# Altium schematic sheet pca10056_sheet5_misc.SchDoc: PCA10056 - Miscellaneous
size A3; Organization: Nordic Semiconductor; DocumentNumber: 5; SheetNumber: 5; SheetTotal: 7; CompanyName: Nordic Semiconductor
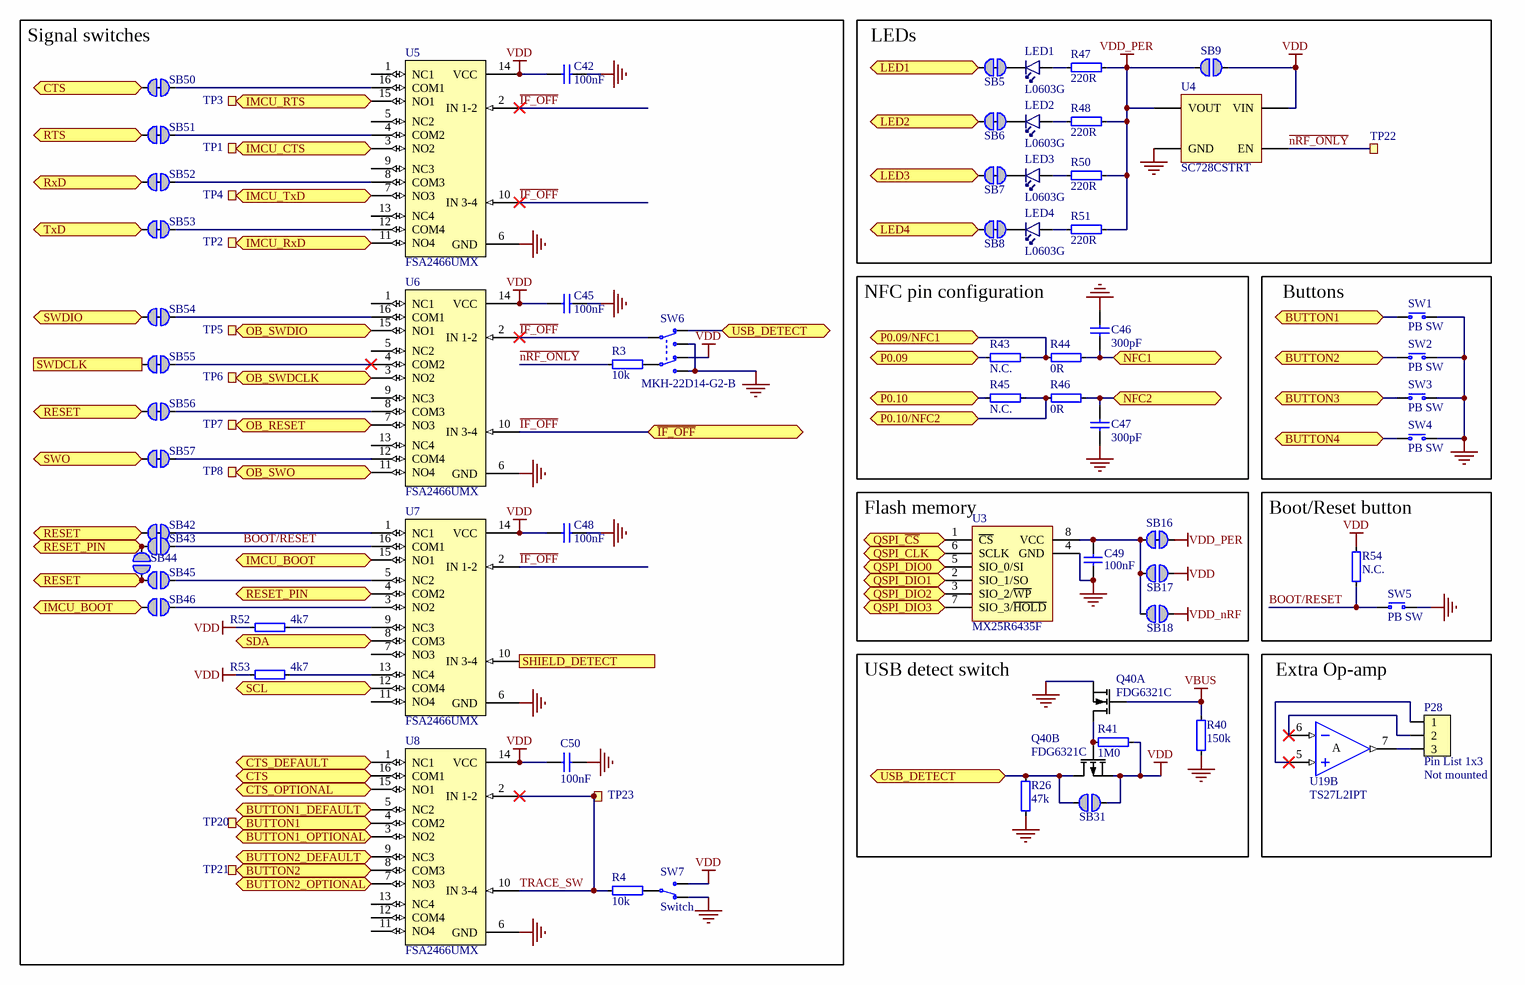
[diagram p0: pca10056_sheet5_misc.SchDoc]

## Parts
C42  100nF  [CAPC1005X04L]
C45  100nF  [CAPC1005X04L]
C46  300pF  [CAPC1005X04L]
C47  300pF  [CAPC1005X04L]
C48  100nF  [CAPC1005X04L]
C49  100nF  [CAPC1005X04L]
C50  100nF  [CAPC1005X04L]
LED1  L0603G  [LED_0603_G]
LED2  L0603G  [LED_0603_G]
LED3  L0603G  [LED_0603_G]
LED4  L0603G  [LED_0603_G]
P28  Pin List 1x3  Assembly: Not mounted  [LIST_1x3-NC]
Q40  FDG6321C  [SOT65P210X100-6N]  (parts A,B of 2)
R3  10k  [RESC1005X04L]
R4  10k  [RESC1005X04L]
R26  47k  [RESC1005X04L]
R40  150k  [RESC1005X04L]
R41  1M0  [RESC1005X04L]
R43  N.C.  [RESC1005X04L]
R44  0R  [RESC1005X04L]
R45  N.C.  [RESC1005X04L]
R46  0R  [RESC1005X04L]
R47  220R  [RESC1005X04L]
R48  220R  [RESC1005X04L]
R50  220R  [RESC1005X04L]
R51  220R  [RESC1005X04L]
R52  4k7  [RESC1005X04L]
R53  4k7  [RESC1005X04L]
R54  N.C.  [RESC1005X04L]
SB5  Solderbridge  [Solderbridge_Shorted]  (value not drawn)  (net tie, no BOM)
SB6  Solderbridge  [Solderbridge_Shorted]  (value not drawn)  (net tie, no BOM)
SB7  Solderbridge  [Solderbridge_Shorted]  (value not drawn)  (net tie, no BOM)
SB8  Solderbridge  [Solderbridge_Shorted]  (value not drawn)  (net tie, no BOM)
SB9  Solderbridge  [Solderbridge]  (value not drawn)  (no BOM)
SB16  Solderbridge  [Solderbridge_Shorted]  (value not drawn)  (net tie, no BOM)
SB17  Solderbridge  [Solderbridge]  (value not drawn)  (no BOM)
SB18  Solderbridge  [Solderbridge]  (value not drawn)  (no BOM)
SB31  Solderbridge  [Solderbridge]  (value not drawn)  (no BOM)
SB42  Solderbridge  [Solderbridge_Shorted]  (value not drawn)  (net tie, no BOM)
SB43  Solderbridge  [Solderbridge]  (value not drawn)  (no BOM)
SB44  Solderbridge  [Solderbridge]  (value not drawn)  (no BOM)
SB45  Solderbridge  [Solderbridge]  (value not drawn)  (no BOM)
SB46  Solderbridge  [Solderbridge]  (value not drawn)  (no BOM)
SB50  Solderbridge  [Solderbridge_Shorted]  (value not drawn)  (net tie, no BOM)
SB51  Solderbridge  [Solderbridge_Shorted]  (value not drawn)  (net tie, no BOM)
SB52  Solderbridge  [Solderbridge_Shorted]  (value not drawn)  (net tie, no BOM)
SB53  Solderbridge  [Solderbridge_Shorted]  (value not drawn)  (net tie, no BOM)
SB54  Solderbridge  [Solderbridge_Shorted]  (value not drawn)  (net tie, no BOM)
SB55  Solderbridge  [Solderbridge_Shorted]  (value not drawn)  (net tie, no BOM)
SB56  Solderbridge  [Solderbridge_Shorted]  (value not drawn)  (net tie, no BOM)
SB57  Solderbridge  [Solderbridge_Shorted]  (value not drawn)  (net tie, no BOM)
SW1  PB SW  [Switch-PB-6.2x6.3mm-SMD]
SW2  PB SW  [Switch-PB-6.2x6.3mm-SMD]
SW3  PB SW  [Switch-PB-6.2x6.3mm-SMD]
SW4  PB SW  [Switch-PB-6.2x6.3mm-SMD]
SW5  PB SW  [Switch-PB-6.2x6.3mm-SMD]
SW6  MKH-22D14-G2-B  [MKH-22D14-G2-B]
SW7  Switch  [CJS-120xA]
TP1  Ø1.0mm,SMD  [TP_SMD_Ø1.0mm]  (value not drawn)  (no BOM)
TP2  Ø1.0mm,SMD  [TP_SMD_Ø1.0mm]  (value not drawn)  (no BOM)
TP3  Ø1.0mm,SMD  [TP_SMD_Ø1.0mm]  (value not drawn)  (no BOM)
TP4  Ø1.0mm,SMD  [TP_SMD_Ø1.0mm]  (value not drawn)  (no BOM)
TP5  Ø1.0mm,SMD  [TP_SMD_Ø1.0mm]  (value not drawn)  (no BOM)
TP6  Ø1.0mm,SMD  [TP_SMD_Ø1.0mm]  (value not drawn)  (no BOM)
TP7  Ø1.0mm,SMD  [TP_SMD_Ø1.0mm]  (value not drawn)  (no BOM)
TP8  Ø1.0mm,SMD  [TP_SMD_Ø1.0mm]  (value not drawn)  (no BOM)
TP20  Ø1.0mm,SMD  [TP_SMD_Ø1.0mm]  (value not drawn)  (no BOM)
TP21  Ø1.0mm,SMD  [TP_SMD_Ø1.0mm]  (value not drawn)  (no BOM)
TP22  Ø1.0mm,SMD  [TP_SMD_Ø1.0mm]  (value not drawn)  (no BOM)
TP23  Ø1.0mm,SMD  [TP_SMD_Ø1.0mm]  (value not drawn)  (no BOM)
U3  MX25R6435F  [SON127P600X80_HS-9N]
U4  SC728CSTRT  [BGA4C40P2X2_76X76X62]
U5  FSA2466UMX  [XQFN40P180X260X50-16N]
U6  FSA2466UMX  [XQFN40P180X260X50-16N]
U7  FSA2466UMX  [XQFN40P180X260X50-16N]
U8  FSA2466UMX  [XQFN40P180X260X50-16N]
U19  TS27L2IPT  [TSOP65P640X120-8N]  (part B of 2)

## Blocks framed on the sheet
Signal switches: C42 C45 C48 C50 R3 R4 R52 R53 SB42-SB46 SB50-SB57 SW6 SW7 TP1-TP8 TP20 TP21 TP23 U5-U8
LEDs: LED1-LED4 R47 R48 R50 R51 SB5-SB9 TP22 U4
NFC pin configuration: C46 C47 R43-R46
Buttons: SW1-SW4
Flash memory: C49 SB16-SB18 U3
Boot/Reset button: R54 SW5
USB detect switch: Q40 R26 R40 R41 SB31
Extra Op-amp: P28 U19

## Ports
BUTTON1 (bidir), BUTTON1_DEFAULT (bidir), BUTTON1_OPTIONAL (bidir), BUTTON2 (bidir), BUTTON2_DEFAULT (bidir), BUTTON2_OPTIONAL (bidir), BUTTON3 (bidir), BUTTON4 (bidir), CTS (bidir), CTS_DEFAULT (bidir), CTS_OPTIONAL (bidir), IMCU_BOOT (bidir), IMCU_CTS (bidir), IMCU_RTS (bidir), IMCU_RxD (bidir), IMCU_TxD (bidir), LED1 (bidir), LED2 (bidir), LED3 (bidir), LED4 (bidir), NFC1 (bidir), NFC2 (bidir), OB_RESET (bidir), OB_SWDCLK (bidir), OB_SWDIO (bidir), OB_SWO (bidir), P0.09 (bidir), P0.09/NFC1 (bidir), P0.10 (bidir), P0.10/NFC2 (bidir), QSPI_CLK (bidir), QSPI_DIO0 (bidir), QSPI_DIO1 (bidir), QSPI_DIO2 (bidir), QSPI_DIO3 (bidir), QSPI_~{CS} (bidir), RESET (bidir), RESET_PIN (bidir), RTS (bidir), RxD (bidir), SCL (bidir), SDA (bidir), SHIELD_DETECT (in), SWDCLK (out), SWDIO (bidir), SWO (bidir), TxD (bidir), USB_DETECT (bidir), ~{IF_OFF} (bidir)

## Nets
GND: C42.1 C45.1 C46.2 C47.1 C48.1 C49.1 C50.1 Q40.1(S1) R26.2 R40.2 SW1.1(N.O) SW2.1(N.O) SW3.1(N.O) SW4.1(N.O) SW5.1(N.O) SW6.1(N.O-1) SW6.4(N.O-2) SW7.1(N.C) U3.4(GND) U3.9(GND) U4.B1(GND) U5.6(GND) U6.6(GND) U7.6(GND) U8.6(GND)
VBUS: Q40.2(G1) R40.1
VDD: C42.2 C45.2 C48.2 C50.2 Q40.4(S2) R41.1 R52.1 R53.1 R54.2 SB9.1 SB17.1 SB31.1 SW6.6(N.C-2) SW7.3(N.O) U4.A2(VIN) U5.14(VCC) U6.14(VCC) U7.14(VCC) U8.14(VCC)
VDD_nRF: SB18.1
VDD_PER: R47.2 R48.2 R50.2 R51.2 SB9.2 SB16.1 U4.A1(VOUT)
BOOT/RESET: R54.1 SB43.1 SW5.2(COM) U7.16(COM1)
BUTTON1: SW1.2(COM) TP20.1 U8.4(COM2) ; port BUTTON1
BUTTON1_DEFAULT: U8.5(NC2) ; port BUTTON1_DEFAULT
BUTTON1_OPTIONAL: U8.3(NO2) ; port BUTTON1_OPTIONAL
BUTTON2: SW2.2(COM) TP21.1 U8.8(COM3) ; port BUTTON2
BUTTON2_DEFAULT: U8.9(NC3) ; port BUTTON2_DEFAULT
BUTTON2_OPTIONAL: U8.7(NO3) ; port BUTTON2_OPTIONAL
BUTTON3: SW3.2(COM) ; port BUTTON3
BUTTON4: SW4.2(COM) ; port BUTTON4
CTS: SB50.1 U8.16(COM1) ; port CTS
CTS_DEFAULT: U8.1(NC1) ; port CTS_DEFAULT
CTS_OPTIONAL: U8.15(NO1) ; port CTS_OPTIONAL
~{IF_OFF}: SW6.2(COM-1) U5.2(IN_1-2) U5.10(IN_3-4) U6.2(IN_1-2) U6.10(IN_3-4) U7.2(IN_1-2) ; port ~{IF_OFF}
IMCU_BOOT: SB46.2 U7.15(NO1) ; port IMCU_BOOT
IMCU_CTS: TP1.1 U5.3(NO2) ; port IMCU_CTS
IMCU_RTS: TP3.1 U5.15(NO1) ; port IMCU_RTS
IMCU_RxD: TP2.1 U5.11(NO4) ; port IMCU_RxD
IMCU_TxD: TP4.1 U5.7(NO3) ; port IMCU_TxD
LED1: SB5.1 ; port LED1
LED2: SB6.1 ; port LED2
LED3: SB7.1 ; port LED3
LED4: SB8.1 ; port LED4
~{nRF_ONLY}: R3.1 TP22.1 U4.B2(EN)
NFC1: C46.1 R44.1 ; port NFC1
NFC2: C47.2 R46.1 ; port NFC2
OB_RESET: TP7.1 U6.7(NO3) ; port OB_RESET
OB_SWDCLK: TP6.1 U6.3(NO2) ; port OB_SWDCLK
OB_SWDIO: TP5.1 U6.15(NO1) ; port OB_SWDIO
OB_SWO: TP8.1 U6.11(NO4) ; port OB_SWO
P0.09: R43.1 ; port P0.09
P0.09/NFC1: R43.2 R44.2 ; port P0.09/NFC1
P0.10: R45.1 ; port P0.10
P0.10/NFC2: R45.2 R46.2 ; port P0.10/NFC2
QSPI_~{CS}: U3.1(~{CS}) ; port QSPI_~{CS}
QSPI_CLK: U3.6(SCLK) ; port QSPI_CLK
QSPI_DIO0: U3.5(SIO_0/SI) ; port QSPI_DIO0
QSPI_DIO1: U3.2(SIO_1/SO) ; port QSPI_DIO1
QSPI_DIO2: U3.3(SIO_2/~{WP}) ; port QSPI_DIO2
QSPI_DIO3: U3.7(SIO_3/~{HOLD}) ; port QSPI_DIO3
RESET: SB42.2 SB44.2 SB45.2 SB56.1 ; port RESET
RESET_PIN: SB43.2 SB44.1 U7.4(COM2) ; port RESET_PIN
RTS: SB51.1 ; port RTS
RxD: SB52.1 ; port RxD
SCL: U7.12(COM4) ; port SCL
SDA: U7.8(COM3) ; port SDA
SHIELD_DETECT: U7.10(IN_3-4) ; port SHIELD_DETECT
SWDCLK: SB55.1 ; port SWDCLK
SWDIO: SB54.1 ; port SWDIO
SWO: SB57.1 ; port SWO
TRACE_SW: R4.1 TP23.1 U8.2(IN_1-2) U8.10(IN_3-4)
TxD: SB53.1 ; port TxD
USB_DETECT: Q40.3(D2) R26.1 SB31.2 SW6.3(N.C-1) ; port USB_DETECT
NetC49_2: C49.2 SB16.2 SB17.2 SB18.2 U3.8(VCC)
NetLED1_1: LED1.1(C) SB5.2
NetLED1_2: LED1.2(A) R47.1
NetLED2_1: LED2.1(C) SB6.2
NetLED2_2: LED2.2(A) R48.1
NetLED3_1: LED3.1(C) SB7.2
NetLED3_2: LED3.2(A) R50.1
NetLED4_1: LED4.1(C) SB8.2
NetLED4_2: LED4.2(A) R51.1
NetP28_1: P28.1 U19.5(IN2+)
NetP28_2: P28.2 U19.6(IN2-)
NetP28_3: P28.3 U19.7(OUT2)
NetQ40_5: Q40.5(G2) Q40.6(D1) R41.2
NetR3_2: R3.2 SW6.5(COM-2)
NetR4_2: R4.2 SW7.2(COM)
NetR52_2: R52.2 U7.9(NC3)
NetR53_2: R53.2 U7.13(NC4)
NetSB42_1: SB42.1 U7.1(NC1)
NetSB45_1: SB45.1 U7.5(NC2)
NetSB46_1: SB46.1 U7.3(NO2)
NetSB50_2: SB50.2 U5.16(COM1)
NetSB51_2: SB51.2 U5.4(COM2)
NetSB52_2: SB52.2 U5.8(COM3)
NetSB53_2: SB53.2 U5.12(COM4)
NetSB54_2: SB54.2 U6.16(COM1)
NetSB55_2: SB55.2 U6.4(COM2)
NetSB56_2: SB56.2 U6.8(COM3)
NetSB57_2: SB57.2 U6.12(COM4)

Not connected (* = marked no-connect by the designer): U5 1(NC1) 5(NC2) 9(NC3) 13(NC4); U6 1(NC1) 5(NC2) 9(NC3) 13(NC4); U7 7(NO3) 11(NO4); U8 11(NO4) 12(COM4) 13(NC4)

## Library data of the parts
C42 C45 C48-C50 = C0402-100n: Capacitor, X7R, ±10%; Part number IPS: 00000005296; Note: 16V; Artikkelnr Noca: 20039200; Artikkelnr Simpro: N.A.
C46 C47 = C0402-300p: Capacitor, NP0, ±5%; Note: 50V; Artikkelnr Noca: 20020004; Artikkelnr Simpro: N.A.
LED1-LED4 = VS 25C7M5: LED, Green, 0603, 573nm, Vf=2.0V, 24mcd, - 40 to +85°C; Manufacturer: Victory Electronics; Artikkelnr Noca: N.A.
P28 = Pin List 1x3, N.C.: Pin List 1x3, 2.54mm (100mil); Artikkelnr Noca: N.A.
Q40 = FDG6321C: Fairchild, FDG6321C, Dual N & P Channel Digital FET; 2nd source part number: FDG6321CCT-ND; Artikkelnr Noca: 35029089; Artikkelnr Simpro: N.A.
R3 R4 = R0402-10k: Resistor, ±1%, 0.063W; Part number IPS: 00000002093; Note: Chip Res 1%; Artikkelnr Noca: 27049097; Artikkelnr Simpro: N.A.; Value Ohm: 10000
R26 = R0402-47k: Resistor, ±1%, 0.063W; Note: Chip Res 1%; Artikkelnr Noca: 27049113; Artikkelnr Simpro: N.A.; Value Ohm: 47000
R40 = R0402-150k: Resistor, ±1%, 0.063W; Note: Chip Res 1%; Artikkelnr Noca: 27049125; Artikkelnr Simpro: N.A.; Value Ohm: 150000
R41 = R0402-1M0: Resistor, ±1%, 0.063W; Part number IPS: 00000006807; Note: Chip Res 1%; Artikkelnr Noca: 27049145; Artikkelnr Simpro: N.A.; Value Ohm: 1000000
R43 R45 R54 = R0402-N.C.: Not mounted; Note: Chip Res; Artikkelnr Noca: N.A.; Assembly: Not mounted
R44 R46 = R0402-0R: Resistor, ±5%, 0.063W; Note: Chip Res 5%; Artikkelnr Noca: 27049000; Artikkelnr Simpro: N.A.; Value Ohm: 0
R47 R48 R50 R51 = R0402-220: Resistor, ±1%, 0.063W; Note: Chip Res 1%; Artikkelnr Noca: 27049057; Artikkelnr Simpro: N.A.; Value Ohm: 220
R52 R53 = R0402-4k7: Resistor, ±1%, 0.063W; Part number IPS: 00000003433; Note: Chip Res 1%; Artikkelnr Noca: 27049089; Artikkelnr Simpro: N.A.; Value Ohm: 4700
SB5-SB8 SB16 SB42 SB50-SB57 = Solderbridge Shorted: Shorted Solderbridge; Artikkelnr Noca: N.A.
SB9 SB17 SB18 SB31 SB43-SB46 = Solderbridge: Artikkelnr Noca: N.A.
SW1-SW5 = Switch-PB-6.2x6.3mm-SMD: Tactile Switch, SPNO, SMD, 160gf, 6.2x6.3x2.5mm; Manufacturer: Dailywell; Manufacturer Part Number: TS604VM1-025BR-R; 2nd source part number: 688-SKHUALE010; Part number IPS: 00000007812; Artikkelnr Noca: 50019106; Artikkelnr Simpro: N.A.
SW6 = MKH-22D14-G2-B: Slide Switch DPDT; Manufacturer: Dailywell; Artikkelnr Noca: 50019112; Artikkelnr Simpro: N.A.
SW7 = CJS-1200TA: SMD slide Switch (ON-ON); Manufacturer: Copal Electronics Inc; Artikkelnr Noca: 50019068; Artikkelnr Simpro: N.A.
TP1-TP8 TP20-TP23 = TP_SMD_Ø1.0MM: 1.0mm circular SMD testpad; Manufacturer: Nordic Semiconductor; Artikkelnr Noca: N.A.
U3 = MX25R6435FZNIL0: Ultra low power, 64M-bit, serial multi I/O flash memory; Manufacturer: Macronix; Artikkelnr Noca: 15020015; Artikkelnr Simpro: N.A.
U4 = SC728CSTRT: Semtech, 2A Low Vin, Very Low Ron, Load Switch, 4DSBGA; Manufacturer: Semtech Corporation; 2nd source part number: 947-SC728CSTRT; Artikkelnr Noca: 15070081; Artikkelnr Simpro: N.A.
U5-U8 = FSA2466UMX: Data / Audio Low-Voltage Dual DPDT Analog Switch; Manufacturer: Fairchild Semiconductor; 2nd source part number: 512-FSA2466UMX; Artikkelnr Noca: 15070069; Artikkelnr Simpro: N.A.
U19 = TS27L2IPT: Precision very low power CMOS dual operational amplifier; Manufacturer: STMicroelectronics; Artikkelnr Noca: 17010019; Artikkelnr Simpro: N.A.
